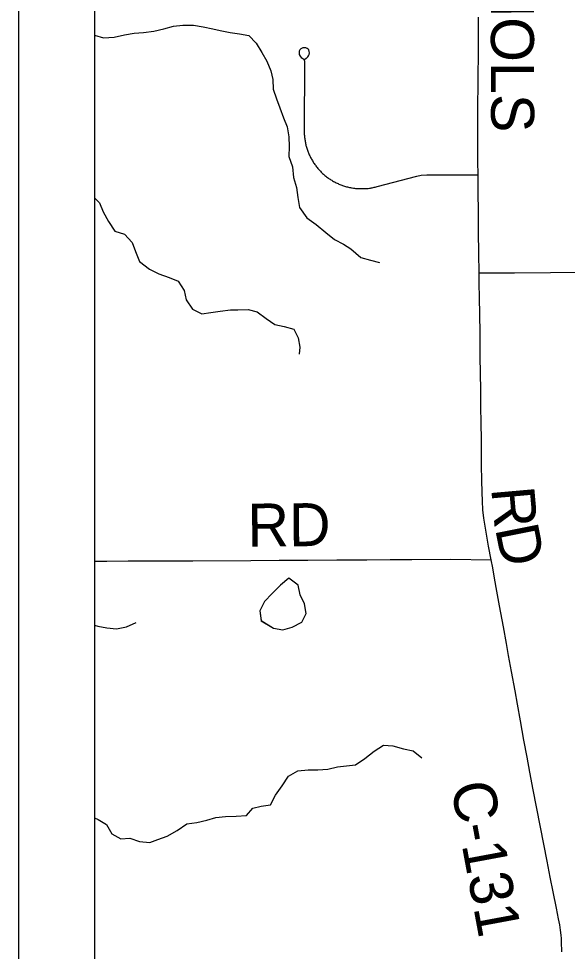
# Model space of a CAD drawing. Extents: x 0 to 34, y 0 to 22.
# Drawn here: x 2 to 2.725, y 15.885 to 17.117 of the extents above; entities that cross this region are included whole.
import ezdxf

# ---------------------------------------------------------------- set-up
doc = ezdxf.new("R2010")
doc.units = 0
for name, color, linetype in [('GM_X_Corporation', 7, 'Continuous'), ('GM_X_County_Road', 7, 'Continuous'), ('GM_X_County_Road_Text', 7, 'Continuous'), ('GM_X_Minor_Lake', 7, 'Continuous'), ('GM_X_Minor_River', 7, 'Continuous'), ('GM_X_Township_Road', 7, 'Continuous'), ('GM_X_Township_Road_Text', 7, 'Continuous'), ('SH_Data', 7, 'Continuous')]:
    doc.layers.add(name, color=color, linetype=linetype)

msp = doc.modelspace()

# ---------------------------------------------------------------- linework, layer by layer
at = {"layer": 'GM_X_Corporation'}
msp.add_lwpolyline([(2.1, 20.9), (2.1, 14.1), (7.9734, 14.1), (7.9726, 14.5453), (7.9765, 15.2637), (7.9792, 15.5481), (7.979, 15.5988), (7.9808, 15.7192), (7.9807, 15.9078), (7.9821, 16.2487), (7.9825, 16.3395), (7.9818, 16.3982), (7.9825, 16.6077), (7.9838, 16.7968), (7.9877, 17.3871), (7.9891, 17.5498), (7.991, 17.7727), (7.9901, 18.1613)], dxfattribs=at)
msp.add_lwpolyline([(2.1, 19.0167), (2.1, 14.5179), (2.2213, 14.5194), (2.2958, 14.5199), (2.3573, 14.5203), (2.3767, 14.5206), (2.4262, 14.5205), (2.6122, 14.5212), (2.8483, 14.5213), (2.8655, 14.5214), (2.8502, 15.8768), (2.8488, 16.2), (2.8487, 16.2273), (2.8487, 16.232), (2.8477, 16.3135), (2.8476, 16.3157), (2.8477, 16.7834), (2.837, 17.9259), (2.8293, 18.7154), (2.8247, 19.0323), (2.4392, 19.024), (2.4288, 19.0238), (2.421, 19.0236)], close=True, dxfattribs=at)
at = {"layer": 'GM_X_County_Road'}
for points in [[(2.7177, 15.8846), (2.7173, 15.8978), (2.7171, 15.9024), (2.7167, 15.9066), (2.7159, 15.9131), (2.7148, 15.9204), (2.7133, 15.9282), (2.7106, 15.9424), (2.7063, 15.9637), (2.7023, 15.9833), (2.6982, 16.0046), (2.6894, 16.0494), (2.6842, 16.0762), (2.6798, 16.0986), (2.6755, 16.1218), (2.6717, 16.1419), (2.6675, 16.1641), (2.663, 16.1898), (2.6591, 16.2115), (2.6558, 16.2294), (2.6511, 16.255), (2.6473, 16.2758), (2.6444, 16.2917), (2.6403, 16.3139), (2.6352, 16.3416), (2.6318, 16.3609), (2.6286, 16.3782), (2.6262, 16.3916), (2.6242, 16.4024), (2.6209, 16.4201), (2.6176, 16.4389), (2.6146, 16.4574), (2.6134, 16.4684), (2.6126, 16.4797), (2.6122, 16.4914), (2.6119, 16.5069), (2.6116, 16.5272), (2.6115, 16.5433), (2.6113, 16.563), (2.6111, 16.5811), (2.6106, 16.6065), (2.6104, 16.6271), (2.6102, 16.6479), (2.6098, 16.671), (2.6095, 16.7017), (2.6092, 16.7265), (2.6088, 16.748), (2.6084, 16.7676), (2.6084, 16.7813), (2.608, 16.8067), (2.6077, 16.8354), (2.6075, 16.8599), (2.6072, 16.8892), (2.607, 16.9104), (2.6068, 16.9283), (2.6065, 16.9547), (2.6067, 16.9903), (2.6068, 17.0072), (2.6069, 17.0242), (2.6072, 17.0457), (2.6073, 17.0649), (2.6075, 17.0962), (2.6076, 17.1188)], [(2.6084, 16.7813), (2.6295, 16.781), (2.6551, 16.7811), (2.7026, 16.7818), (2.7666, 16.7822), (2.7924, 16.7825), (2.8017, 16.7826), (2.8104, 16.7828), (2.827, 16.7831), (2.8415, 16.7834)]]:
    msp.add_lwpolyline(points, dxfattribs=at)
at = {"layer": 'GM_X_Minor_Lake'}
for points in [[(2.3693, 16.3689), (2.357, 16.3782), (2.3459, 16.3689), (2.3347, 16.3577), (2.3247, 16.3473), (2.3188, 16.335), (2.3206, 16.3218)], [(2.3693, 16.3689), (2.357, 16.3782), (2.3459, 16.3689), (2.3347, 16.3577), (2.3247, 16.3473), (2.3188, 16.335), (2.3206, 16.3222)], [(2.3203, 16.322), (2.3367, 16.3118), (2.3488, 16.3097), (2.3612, 16.3134), (2.374, 16.3201), (2.3798, 16.3312), (2.3777, 16.344), (2.3718, 16.3561), (2.3693, 16.3689)], [(2.3206, 16.3218), (2.3367, 16.3118), (2.3488, 16.3097), (2.3612, 16.3134), (2.374, 16.3201), (2.3798, 16.3312), (2.3777, 16.344), (2.3718, 16.3561), (2.3693, 16.3689)]]:
    msp.add_lwpolyline(points, dxfattribs=at)
at = {"layer": 'GM_X_Minor_River'}
for points in [[(2.1, 17.0948), (2.1122, 17.0914), (2.1262, 17.0924), (2.1398, 17.0953), (2.1526, 17.0974), (2.1651, 17.0984), (2.1787, 17.1002), (2.1918, 17.1031), (2.2046, 17.1067), (2.2171, 17.1081), (2.2311, 17.1083), (2.2436, 17.1059), (2.2565, 17.1031), (2.2664, 17.101), (2.2793, 17.0985), (2.2918, 17.0969), (2.304, 17.0944), (2.3136, 17.0843), (2.3214, 17.0719), (2.328, 17.0607), (2.3332, 17.0479), (2.336, 17.0362), (2.3362, 17.0236), (2.3406, 17.0108), (2.345, 16.9991), (2.3501, 16.9859), (2.3549, 16.9739), (2.357, 16.9606), (2.3572, 16.9481), (2.3571, 16.9348), (2.3619, 16.9209), (2.3629, 16.9072), (2.3669, 16.8937), (2.3686, 16.8808), (2.3711, 16.8672), (2.3808, 16.8537), (2.3931, 16.8448), (2.4058, 16.8344), (2.4173, 16.8251), (2.4291, 16.8189), (2.439, 16.813), (2.4521, 16.8014), (2.465, 16.7979), (2.4768, 16.7947)], [(2.1, 16.8803), (2.107, 16.8735), (2.1117, 16.8615), (2.1188, 16.8491), (2.1269, 16.8363), (2.1399, 16.8324), (2.1499, 16.8212), (2.1543, 16.8091), (2.1598, 16.7959), (2.1728, 16.7859), (2.185, 16.78), (2.1988, 16.775), (2.2109, 16.7703), (2.2187, 16.7579), (2.2212, 16.7454), (2.2298, 16.733), (2.242, 16.7272), (2.2537, 16.7289), (2.2661, 16.7306), (2.2797, 16.7324), (2.2895, 16.7322), (2.3031, 16.7328), (2.3153, 16.7296), (2.3268, 16.7207), (2.3383, 16.7129), (2.3508, 16.7105), (2.3634, 16.7069), (2.3692, 16.6953), (2.3713, 16.6831), (2.3708, 16.6736)], [(2.1, 16.316), (2.1044, 16.3146), (2.1165, 16.3125), (2.1294, 16.3112), (2.1426, 16.3137), (2.1553, 16.3196)], [(2.1, 16.0617), (2.1051, 16.0596), (2.1161, 16.0529), (2.1232, 16.0405), (2.135, 16.0339), (2.1471, 16.0349), (2.1597, 16.0302), (2.1733, 16.0289), (2.1838, 16.0329), (2.1962, 16.0373), (2.2093, 16.0451), (2.2224, 16.0537), (2.2353, 16.0554), (2.2484, 16.0587), (2.2605, 16.0619), (2.2733, 16.0633), (2.2873, 16.0639), (2.3009, 16.0649), (2.3094, 16.0745), (2.3204, 16.077), (2.3328, 16.0788), (2.3394, 16.0914), (2.3483, 16.1037), (2.3567, 16.1167), (2.3687, 16.1238), (2.3823, 16.1248), (2.3952, 16.125), (2.4084, 16.126), (2.4212, 16.1289), (2.4329, 16.1302), (2.445, 16.1316), (2.4573, 16.1398), (2.4696, 16.1498), (2.482, 16.1576), (2.4941, 16.1567), (2.5082, 16.1528), (2.5211, 16.15), (2.5326, 16.1407)]]:
    msp.add_lwpolyline(points, dxfattribs=at)
at = {"layer": 'GM_X_Township_Road'}
for points in [[(2.3775, 17.063), (2.3799, 17.0644), (2.3809, 17.0651), (2.382, 17.0661), (2.3831, 17.0676), (2.3839, 17.0696), (2.3842, 17.0716), (2.384, 17.0734), (2.3833, 17.0754), (2.3823, 17.0766), (2.3811, 17.0774), (2.3793, 17.0781), (2.3755, 17.0781), (2.3738, 17.0775), (2.3726, 17.0768), (2.3715, 17.0757), (2.3707, 17.0737), (2.3704, 17.0714), (2.3708, 17.0693), (2.3717, 17.0673), (2.3734, 17.0653), (2.3755, 17.0641), (2.3768, 17.0631), (2.3774, 17.062), (2.3775, 17.0605), (2.3773, 16.9678), (2.3774, 16.9638), (2.3775, 16.9625), (2.3776, 16.9612), (2.3778, 16.9599), (2.3779, 16.9585), (2.3781, 16.9572), (2.3783, 16.9559), (2.3785, 16.9546), (2.3788, 16.9533), (2.379, 16.952), (2.3793, 16.9507), (2.3796, 16.9494), (2.38, 16.9482), (2.3803, 16.9469), (2.3807, 16.9456), (2.3811, 16.9444), (2.3815, 16.9431), (2.382, 16.9419), (2.3825, 16.9406), (2.3829, 16.9394), (2.3835, 16.9382), (2.384, 16.937), (2.3845, 16.9358), (2.3851, 16.9346), (2.3857, 16.9334), (2.3863, 16.9322), (2.387, 16.931), (2.3876, 16.9299), (2.3883, 16.9288), (2.389, 16.9276), (2.3897, 16.9265), (2.3904, 16.9254), (2.3912, 16.9243), (2.392, 16.9233), (2.3927, 16.9222), (2.3935, 16.9211), (2.3944, 16.9201), (2.3952, 16.9191), (2.3961, 16.9181), (2.397, 16.9171), (2.3979, 16.9161), (2.3988, 16.9152), (2.3997, 16.9142), (2.4007, 16.9133), (2.4016, 16.9124), (2.4026, 16.9115), (2.4036, 16.9106), (2.4046, 16.9098), (2.4056, 16.9089), (2.4067, 16.9081), (2.4082, 16.9069), (2.4093, 16.9062), (2.4104, 16.9054), (2.4115, 16.9047), (2.4126, 16.904), (2.4137, 16.9033), (2.4148, 16.9026), (2.416, 16.9019), (2.4172, 16.9013), (2.4183, 16.9007), (2.4195, 16.9001), (2.4207, 16.8995), (2.4219, 16.8989), (2.4231, 16.8984), (2.4243, 16.8979), (2.4256, 16.8974), (2.4268, 16.8969), (2.428, 16.8965), (2.4293, 16.8961), (2.4305, 16.8956), (2.4318, 16.8953), (2.4331, 16.8949), (2.4344, 16.8946), (2.4357, 16.8942), (2.4369, 16.894), (2.4382, 16.8937), (2.4395, 16.8934), (2.4408, 16.8932), (2.4422, 16.893), (2.4435, 16.8928), (2.4448, 16.8927), (2.4461, 16.8925), (2.4474, 16.8924), (2.4487, 16.8923), (2.4593, 16.8925), (2.4606, 16.8926), (2.4619, 16.8927), (2.4633, 16.8929), (2.4646, 16.8931), (2.4659, 16.8933), (2.4672, 16.8935), (2.4685, 16.8938), (2.4698, 16.8941), (2.4711, 16.8944), (2.4723, 16.8947), (2.4736, 16.895), (2.5259, 16.9087), (2.5317, 16.9099), (2.5394, 16.9107), (2.593, 16.9105), (2.607, 16.9104)], [(2.1, 16.4005), (2.1165, 16.4006), (2.1449, 16.4007), (2.1772, 16.4008), (2.2302, 16.401), (2.3067, 16.4015), (2.3443, 16.4017), (2.3819, 16.4019), (2.4202, 16.4021), (2.4599, 16.4023), (2.4908, 16.4025), (2.5193, 16.4026), (2.571, 16.4029), (2.6242, 16.4024)]]:
    msp.add_lwpolyline(points, dxfattribs=at)
at = {"layer": 'SH_Data'}
for p, q in [((2, 21), (2, 14)), ((2.1, 20.9), (2.1, 14.1))]:
    msp.add_line(p, q, dxfattribs=at)

# ---------------------------------------------------------------- texts
at = {"layer": 'GM_X_County_Road_Text'}
for s, height, rotation, p in [('NICHOLS', 0.05682, 270.1573, (2.6233, 17.3043)), ('R', 0.0568, 275.0492, (2.6242, 16.4967)), ('D', 0.0568, 281.3171, (2.6293, 16.4437)), ('C-131', 0.05682, 280.5512, (2.5706, 16.105))]:
    msp.add_text(s, height=height, rotation=rotation, dxfattribs=at).set_placement(p)
at = {"layer": 'GM_X_Township_Road_Text'}
msp.add_text('RD', height=0.05682, rotation=0.4937, dxfattribs=at).set_placement((2.3025, 16.4196))

doc.saveas('drawing.dxf')
